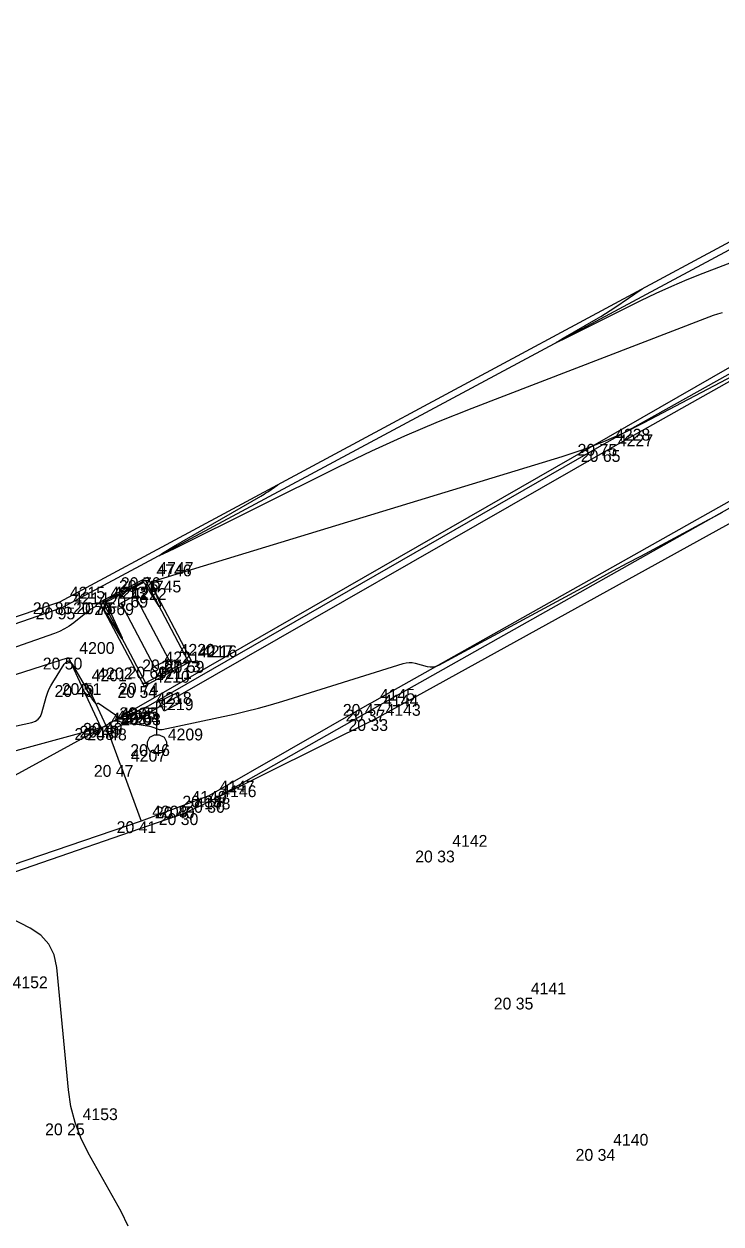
# Model space of a CAD drawing. Extents: x -702257 to -701487, y -1009871 to -1008841.
# Drawn here: x -702041.8 to -702027.07, y -1009661.81 to -1009636.43 of the extents above; entities that cross this region are included whole.
import ezdxf

# ---------------------------------------------------------------- set-up
doc = ezdxf.new("R2010")
doc.units = 0
for name, color, linetype in [('Ex_Major Contours', 7, 'Continuous'), ('Ex_Minor Contours', 7, 'Continuous'), ('Z_body', 7, 'Continuous'), ('Z_body_cisla', 7, 'Continuous'), ('Z_body_vysky_redukovane', 7, 'Continuous'), ('Z_katastr_hranice', 7, 'Continuous'), ('Z_komunikace', 7, 'Continuous'), ('Z_nastenka', 7, 'Continuous'), ('Z_obruba', 7, 'Continuous'), ('Z_rozhranni', 7, 'Continuous'), ('Z_site_vo_znaky', 7, 'Continuous')]:
    doc.layers.add(name, color=color, linetype=linetype)

# ---------------------------------------------------------------- blocks, each defined once
blk = doc.blocks.new('POINT_DISPLAY')
blk.add_line((0, 0), (0, 0))
blk = doc.blocks.new('Z13')
for p, q in [((0, 0.88), (0.45, 1.1)), ((0.4, 1.07), (0.5, 0.88)), ((0, 0.2), (0, 0.88)), ((0.15, 0.7), (0.05, 0.9)), ((0.5, 0.88), (0.15, 0.7)), ((-0.2, 0.05), (-0.15, 0.15)), ((-0.2, -0.05), (-0.2, 0.05)), ((-0.15, 0.15), (-0.05, 0.2)), ((-0.05, 0.2), (0.05, 0.2)), ((0.05, 0.2), (0.15, 0.15)), ((0.15, 0.15), (0.2, 0.05)), ((0.2, 0.05), (0.2, -0.05)), ((-0.15, -0.15), (-0.2, -0.05)), ((-0.05, -0.2), (-0.15, -0.15)), ((0.05, -0.2), (-0.05, -0.2)), ((0.15, -0.15), (0.05, -0.2)), ((0.2, -0.05), (0.15, -0.15))]:
    blk.add_line(p, q)

msp = doc.modelspace()

# ---------------------------------------------------------------- linework, layer by layer
at = {"layer": 'Ex_Major Contours'}
msp.add_lwpolyline([(-702027.048, -1009642.535), (-702027.142, -1009642.564), (-702027.235, -1009642.595), (-702027.327, -1009642.628), (-702027.419, -1009642.662), (-702032.337, -1009644.558), (-702033.051, -1009644.843), (-702033.757, -1009645.144), (-702034.456, -1009645.462), (-702035.147, -1009645.796), (-702038.615, -1009647.521), (-702038.864, -1009647.642), (-702038.951, -1009647.675), (-702038.875, -1009647.621), (-702038.637, -1009647.48), (-702036.797, -1009646.415), (-702036.76, -1009646.393), (-702036.723, -1009646.37), (-702036.686, -1009646.346), (-702036.65, -1009646.322), (-702036.434, -1009646.175)], dxfattribs=at)
at = {"layer": 'Ex_Minor Contours'}
for points in [[(-702024.828, -1009640.695), (-702027.456, -1009641.708), (-702027.79, -1009641.841), (-702028.12, -1009641.982), (-702028.447, -1009642.131), (-702028.771, -1009642.287), (-702030.394, -1009643.095), (-702030.511, -1009643.152), (-702030.551, -1009643.167), (-702030.516, -1009643.142), (-702030.405, -1009643.076), (-702029.709, -1009642.673), (-702029.609, -1009642.614), (-702029.51, -1009642.553), (-702029.413, -1009642.49), (-702029.316, -1009642.426), (-702028.74, -1009642.032)], [(-702026.813, -1009643.867), (-702028.716, -1009644.874), (-702029.132, -1009645.082), (-702029.557, -1009645.269), (-702029.99, -1009645.436), (-702030.432, -1009645.582), (-702039.008, -1009648.195), (-702039.06, -1009648.22), (-702039.089, -1009648.255), (-702039.095, -1009648.3), (-702039.078, -1009648.355), (-702038.912, -1009648.706), (-702038.91, -1009648.711), (-702038.91, -1009648.716), (-702038.911, -1009648.722), (-702038.913, -1009648.727), (-702038.927, -1009648.747), (-702038.93, -1009648.75), (-702038.933, -1009648.752), (-702038.937, -1009648.75), (-702038.94, -1009648.747), (-702039.154, -1009648.411), (-702039.165, -1009648.394), (-702039.175, -1009648.377), (-702039.186, -1009648.359), (-702039.197, -1009648.342), (-702039.24, -1009648.272), (-702039.252, -1009648.258), (-702039.265, -1009648.251), (-702039.281, -1009648.25), (-702039.298, -1009648.256), (-702040.022, -1009648.634), (-702040.044, -1009648.646), (-702040.065, -1009648.657), (-702040.069, -1009648.66), (-702040.072, -1009648.664), (-702040.072, -1009648.669), (-702040.07, -1009648.674), (-702040.001, -1009648.806), (-702039.988, -1009648.83), (-702039.976, -1009648.855), (-702039.965, -1009648.879), (-702039.954, -1009648.904), (-702039.754, -1009649.346), (-702039.727, -1009649.408), (-702039.722, -1009649.431), (-702039.737, -1009649.413), (-702039.774, -1009649.357), (-702040.078, -1009648.859), (-702040.143, -1009648.781), (-702040.215, -1009648.746), (-702040.295, -1009648.754), (-702040.383, -1009648.805), (-702040.749, -1009649.096), (-702040.843, -1009649.164), (-702040.942, -1009649.224), (-702041.045, -1009649.275), (-702041.153, -1009649.318), (-702042.099, -1009649.649)], [(-702043.781, -1009651.667), (-702041.635, -1009651.2), (-702041.559, -1009651.174), (-702041.497, -1009651.131), (-702041.452, -1009651.072), (-702041.421, -1009650.997), (-702041.33, -1009650.664), (-702041.304, -1009650.582), (-702041.272, -1009650.503), (-702041.235, -1009650.426), (-702041.192, -1009650.352), (-702040.947, -1009649.967), (-702040.904, -1009649.916), (-702040.861, -1009649.899), (-702040.82, -1009649.917), (-702040.779, -1009649.97), (-702040.577, -1009650.317), (-702040.556, -1009650.354), (-702040.536, -1009650.39), (-702040.515, -1009650.427), (-702040.495, -1009650.464), (-702040.397, -1009650.649), (-702040.386, -1009650.668), (-702040.375, -1009650.686), (-702040.363, -1009650.703), (-702040.35, -1009650.72), (-702040.277, -1009650.811), (-702040.274, -1009650.814), (-702040.27, -1009650.816), (-702040.266, -1009650.815), (-702040.261, -1009650.812), (-702040.244, -1009650.798), (-702040.239, -1009650.795), (-702040.235, -1009650.793), (-702040.23, -1009650.794), (-702040.225, -1009650.796), (-702039.865, -1009651.04), (-702039.856, -1009651.048), (-702039.85, -1009651.057), (-702039.848, -1009651.067), (-702039.848, -1009651.079), (-702039.857, -1009651.13), (-702039.858, -1009651.141), (-702039.854, -1009651.151), (-702039.848, -1009651.158), (-702039.837, -1009651.162), (-702039.728, -1009651.195), (-702039.717, -1009651.198), (-702039.705, -1009651.2), (-702039.694, -1009651.201), (-702039.682, -1009651.202), (-702039.635, -1009651.202), (-702039.624, -1009651.202), (-702039.612, -1009651.203), (-702039.6, -1009651.204), (-702039.589, -1009651.206), (-702039.145, -1009651.281), (-702039.122, -1009651.285), (-702039.099, -1009651.291), (-702039.077, -1009651.298), (-702039.054, -1009651.306), (-702038.966, -1009651.341), (-702038.944, -1009651.348), (-702038.921, -1009651.351), (-702038.899, -1009651.351), (-702038.876, -1009651.348), (-702037.361, -1009651.022), (-702037.101, -1009650.963), (-702036.843, -1009650.898), (-702036.587, -1009650.828), (-702036.332, -1009650.751), (-702033.788, -1009649.955), (-702033.725, -1009649.939), (-702033.661, -1009649.933), (-702033.598, -1009649.936), (-702033.534, -1009649.948), (-702033.278, -1009650.015), (-702033.215, -1009650.026), (-702033.153, -1009650.025), (-702033.093, -1009650.011), (-702033.034, -1009649.986), (-702029.915, -1009648.301), (-702029.627, -1009648.145), (-702029.34, -1009647.99), (-702029.052, -1009647.835), (-702028.765, -1009647.681), (-702027.329, -1009646.909), (-702027.184, -1009646.831), (-702027.038, -1009646.754)], [(-702039.596, -1009661.856), (-702039.748, -1009661.54), (-702040.443, -1009660.3), (-702040.599, -1009659.985), (-702040.72, -1009659.658), (-702040.806, -1009659.321), (-702040.858, -1009658.972), (-702041.106, -1009656.381), (-702041.161, -1009656.116), (-702041.273, -1009655.89), (-702041.442, -1009655.702), (-702041.667, -1009655.552), (-702042.682, -1009655.031)]]:
    msp.add_lwpolyline(points, dxfattribs=at)
at = {"layer": 'Z_katastr_hranice'}
for p, q in [((-702040.13, -1009651.3), (-702014.27, -1009636.43)), ((-702083.93, -1009675.3), (-702040.13, -1009651.3)), ((-702040.13, -1009651.3), (-702046.17, -1009652.94))]:
    msp.add_line(p, q, dxfattribs=at)
at = {"layer": 'Z_komunikace'}
for p, q in [((-702025.71, -1009646.34), (-702034.38, -1009651.13)), ((-702034.38, -1009651.13), (-702037.85, -1009652.86)), ((-702038.41, -1009653.12), (-702037.85, -1009652.86)), ((-702043.19, -1009654.77), (-702038.41, -1009653.12))]:
    msp.add_line(p, q, dxfattribs=at)
at = {"layer": 'Z_nastenka'}
for p, q in [((-702039.45, -1009648.52), (-702039.75, -1009648.68)), ((-702039.75, -1009648.68), (-702039.05, -1009650.02)), ((-702038.74, -1009649.87), (-702039.45, -1009648.52)), ((-702039.05, -1009650.02), (-702038.74, -1009649.87))]:
    msp.add_line(p, q, dxfattribs=at)
at = {"layer": 'Z_obruba'}
for p, q in [((-702023.2, -1009639.05), (-702041.05, -1009648.66)), ((-702040.99, -1009648.77), (-702023.16, -1009639.2)), ((-702029.54, -1009645.31), (-702020.76, -1009640.38)), ((-702020.68, -1009640.49), (-702029.47, -1009645.44)), ((-702039.22, -1009650.88), (-702029.54, -1009645.31)), ((-702029.47, -1009645.44), (-702039.18, -1009651.01)), ((-702034.5, -1009650.81), (-702025.95, -1009645.99)), ((-702025.9, -1009646.11), (-702034.44, -1009650.93)), ((-702040.2, -1009648.66), (-702039.19, -1009648.13)), ((-702040.13, -1009648.66), (-702039.23, -1009648.19)), ((-702038.34, -1009649.89), (-702039.23, -1009648.19)), ((-702038.26, -1009649.9), (-702039.19, -1009648.13)), ((-702041.05, -1009648.66), (-702052.09, -1009652.39)), ((-702040.2, -1009648.66), (-702039.26, -1009650.43)), ((-702040.13, -1009648.66), (-702039.23, -1009650.36)), ((-702045.02, -1009650.16), (-702040.99, -1009648.77)), ((-702039.26, -1009650.43), (-702038.26, -1009649.9)), ((-702039.23, -1009650.36), (-702038.34, -1009649.89)), ((-702040.59, -1009650.41), (-702040.48, -1009650.37)), ((-702040.59, -1009650.41), (-702040.17, -1009651.32)), ((-702040.06, -1009651.27), (-702040.48, -1009650.37)), ((-702039.22, -1009650.88), (-702039.99, -1009651.21)), ((-702034.5, -1009650.81), (-702037.89, -1009652.75)), ((-702037.85, -1009652.86), (-702034.44, -1009650.93)), ((-702039.9, -1009651.33), (-702039.99, -1009651.21)), ((-702039.9, -1009651.33), (-702039.18, -1009651.01)), ((-702040.06, -1009651.27), (-702040.17, -1009651.32)), ((-702037.89, -1009652.75), (-702038.49, -1009652.98)), ((-702038.49, -1009652.98), (-702039.32, -1009653.29)), ((-702039.32, -1009653.29), (-702043.24, -1009654.62))]:
    msp.add_line(p, q, dxfattribs=at)
at = {"layer": 'Z_rozhranni'}
for p, q in [((-702044.06, -1009650.85), (-702040.86, -1009649.83)), ((-702040.86, -1009649.83), (-702040.59, -1009650.41)), ((-702039.99, -1009651.21), (-702040.06, -1009651.27)), ((-702039.76, -1009652.1), (-702040.06, -1009651.27)), ((-702039.76, -1009652.1), (-702039.32, -1009653.29))]:
    msp.add_line(p, q, dxfattribs=at)

# ---------------------------------------------------------------- block references
at = {"layer": 'Z_body'}
for p in [(-702029.54, -1009645.31), (-702029.47, -1009645.44), (-702039.23, -1009648.19), (-702039.19, -1009648.13), (-702041.05, -1009648.66), (-702040.2, -1009648.66), (-702040.13, -1009648.66), (-702039.75, -1009648.68), (-702039.45, -1009648.52), (-702040.99, -1009648.77), (-702040.86, -1009649.83), (-702038.74, -1009649.87), (-702038.34, -1009649.89), (-702038.26, -1009649.9), (-702039.05, -1009650.02), (-702040.59, -1009650.41), (-702040.48, -1009650.37), (-702039.26, -1009650.43), (-702039.23, -1009650.36), (-702039.22, -1009650.88), (-702034.5, -1009650.81), (-702034.44, -1009650.93), (-702039.99, -1009651.21), (-702039.18, -1009651.01), (-702034.38, -1009651.13), (-702040.17, -1009651.32), (-702040.06, -1009651.27), (-702039.9, -1009651.33), (-702038.99, -1009651.66), (-702039.76, -1009652.1), (-702037.89, -1009652.75), (-702038.49, -1009652.98), (-702037.85, -1009652.86), (-702038.41, -1009653.12), (-702039.32, -1009653.29), (-702032.97, -1009653.91), (-702031.31, -1009657.02), (-702040.79, -1009659.68), (-702029.58, -1009660.22)]:
    msp.add_blockref('POINT_DISPLAY', p, dxfattribs=at)
at = {"layer": 'Z_site_vo_znaky'}
msp.add_blockref('Z13', (-702038.99, -1009651.66), dxfattribs=at)

# ---------------------------------------------------------------- texts
at = {"layer": 'Z_body_cisla'}
for s, p in [('4228', (-702029.31, -1009645.24)), ('4227', (-702029.25, -1009645.36)), ('4746', (-702039, -1009648.11)), ('4747', (-702038.96, -1009648.06)), ('4745', (-702039.22, -1009648.45)), ('4215', (-702040.83, -1009648.58)), ('4214', (-702040.76, -1009648.7)), ('4213', (-702039.97, -1009648.58)), ('4212', (-702039.91, -1009648.58)), ('4222', (-702039.53, -1009648.61)), ('4200', (-702040.63, -1009649.75)), ('4221', (-702038.83, -1009649.95)), ('4220', (-702038.51, -1009649.79)), ('4217', (-702038.12, -1009649.82)), ('4216', (-702038.04, -1009649.82)), ('4201', (-702040.37, -1009650.33)), ('4202', (-702040.25, -1009650.29)), ('4210', (-702039.04, -1009650.36)), ('4211', (-702039, -1009650.28)), ('4145', (-702034.28, -1009650.74)), ('4218', (-702039, -1009650.81)), ('4219', (-702038.96, -1009650.94)), ('4144', (-702034.21, -1009650.86)), ('4203', (-702039.95, -1009651.24)), ('4206', (-702039.84, -1009651.2)), ('4205', (-702039.76, -1009651.14)), ('4204', (-702039.67, -1009651.25)), ('4143', (-702034.16, -1009651.06)), ('4209', (-702038.76, -1009651.58)), ('4207', (-702039.54, -1009652.03)), ('4147', (-702037.67, -1009652.68)), ('4149', (-702038.26, -1009652.9)), ('4146', (-702037.63, -1009652.78)), ('4208', (-702039.09, -1009653.21)), ('4148', (-702038.18, -1009653.04)), ('4142', (-702032.75, -1009653.83)), ('4152', (-702042.04, -1009656.82)), ('4141', (-702031.09, -1009656.95)), ('4153', (-702040.56, -1009659.61)), ('4140', (-702029.35, -1009660.15))]:
    msp.add_text(s, height=0.25, dxfattribs=at).set_placement(p)
at = {"layer": 'Z_body_vysky_redukovane'}
for s, p in [('20 75', (-702030.103, -1009645.56)), ('20 65', (-702030.033, -1009645.69)), ('20 76', (-702039.792, -1009648.44)), ('20 76', (-702039.752, -1009648.38)), ('20 85', (-702041.613, -1009648.91)), ('20 75', (-702040.763, -1009648.91)), ('20 76', (-702040.693, -1009648.91)), ('20 69', (-702040.312, -1009648.93)), ('20 69', (-702040.013, -1009648.77)), ('20 95', (-702041.552, -1009649.02)), ('20 50', (-702041.402, -1009650.08)), ('20 67', (-702039.302, -1009650.12)), ('20 73', (-702038.903, -1009650.14)), ('20 59', (-702038.823, -1009650.15)), ('20 69', (-702039.613, -1009650.27)), ('20 49', (-702041.153, -1009650.66)), ('20 51', (-702041.001, -1009650.62)), ('20 54', (-702039.823, -1009650.68)), ('20 74', (-702039.792, -1009650.61)), ('20 55', (-702039.783, -1009651.13)), ('20 47', (-702035.062, -1009651.06)), ('20 37', (-702035.002, -1009651.18)), ('20 49', (-702040.552, -1009651.46)), ('20 53', (-702039.743, -1009651.26)), ('20 33', (-702034.943, -1009651.38)), ('20 48', (-702040.733, -1009651.57)), ('20 49', (-702040.623, -1009651.52)), ('20 48', (-702040.463, -1009651.58)), ('20 46', (-702039.552, -1009651.91)), ('20 47', (-702040.323, -1009652.35)), ('20 38', (-702038.453, -1009653)), ('20 40', (-702039.032, -1009653.23)), ('20 30', (-702038.392, -1009653.11)), ('20 30', (-702038.952, -1009653.37)), ('20 41', (-702039.841, -1009653.54)), ('20 33', (-702033.533, -1009654.16)), ('20 35', (-702031.873, -1009657.27)), ('20 25', (-702041.353, -1009659.93)), ('20 34', (-702030.143, -1009660.47))]:
    msp.add_text(s, height=0.25, dxfattribs=at).set_placement(p)

doc.saveas('drawing.dxf')
